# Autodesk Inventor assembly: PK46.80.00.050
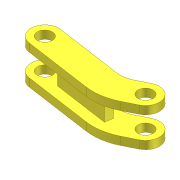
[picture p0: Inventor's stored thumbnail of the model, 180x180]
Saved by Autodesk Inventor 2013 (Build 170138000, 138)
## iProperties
Created: 2005-05
Part Number: PK46.80.00.050
Document SubType Name: Assembly
Designer: salex
Manufacturer: Standard
Standards Organization: Custom
Author: salex
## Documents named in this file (3)
- C:\Product Design Suite 2013 Test Drive\Dynamic Simulation\Workspace\Assy, Chassis, Front\PK46.80.00.050.iam
- C:\Product Design Suite 2013 Test Drive\Dynamic Simulation\Workspace\Assy, Chassis, Front\PK46.80.00.023.ipt
- C:\Product Design Suite 2013 Test Drive\Dynamic Simulation\Workspace\Assy, Chassis, Front\PK46.80.00.024.ipt
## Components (3 placed, 2 different names)
1. PK46.80.00.023:1 — Совмещение:1, Совмещение:3, Совмещение:4, Заподлицо:1
2. PK46.80.00.023:2 — Совмещение:2, Совмещение:3, Совмещение:4, Совмещение:5
3. PK46.80.00.024:1 — Совмещение:1, Совмещение:2, Совмещение:5, Заподлицо:1
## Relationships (6: Mate 5, Flush 1)
- Совмещение:1 [Mate]: PK46.80.00.023:1 ↔ PK46.80.00.024:1
- Совмещение:2 [Mate]: PK46.80.00.023:2 ↔ PK46.80.00.024:1
- Совмещение:3 [Mate]: PK46.80.00.023:1 ↔ PK46.80.00.023:2
- Совмещение:4 [Mate]: PK46.80.00.023:1 ↔ PK46.80.00.023:2
- Совмещение:5 [Mate]: PK46.80.00.023:2 ↔ PK46.80.00.024:1
- Заподлицо:1 [Flush]: PK46.80.00.023:1 ↔ PK46.80.00.024:1
